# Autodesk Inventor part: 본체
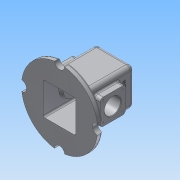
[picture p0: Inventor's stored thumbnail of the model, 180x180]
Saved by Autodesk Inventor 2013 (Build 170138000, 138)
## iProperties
Created: 2018-07
Part Number: 본체
Material: 알루미늄 6061
Document SubType Name: Modeling
Designer: Administrator
Density: 2.71 g/cm^3
Mass: 912.745 g
Surface Area: 1017.53 cm^2
Volume: 336.806 cm^3
Author: Administrator
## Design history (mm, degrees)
sketch "스케치1"
  geometry: L1 (-37, -37)-(37, -37); L2 (37, -37)-(37, 37); L3 (37, 37)-(-37, 37); L4 (-37, 37)-(-37, -37); L5 (-37, -37)-(37, 37); L6 (37, -37)-(-37, 37); 1 further point
  constraints: 12 end point, 2 midpoint, 2 parallel, 1 horizontal, 1 perpendicular
  dimensions: "d0" = 74 distance of L2.end L3.end; "d2" = 74 distance of L1.end L2.end
extrude "돌출1" new body sketch "스케치1" distance "d3" = 110; taper "d4" = 0 deg
feature "쉘1" dims "d5" = 5
sketch "스케치2"
  geometry: L1 (0, 0)-(74, 0) reference; L2 (12, 30)-(62, 30); L3 (62, 30)-(62, 80); L4 (62, 80)-(12, 80); L5 (12, 80)-(12, 30); L6 (12, 30)-(62, 80); L7 (62, 30)-(12, 80); 4 further points
  constraints: 12 end point, 4 midpoint, 2 parallel, 1 horizontal, 1 perpendicular, 1 vertical alignment
  dimensions: "d6" = 50 distance of L2.end L3.end; "d8" = 50 distance of L3.end L4.end; "d9" = 55 distance from line of L1 point (37, 55)
extrude "돌출2" join sketch "스케치2" distance "d10" = 13; taper "d11" = 0 deg
sketch "스케치3"
  geometry: L1 (0, 0)-(-64, 0) reference; C1 r 25 at (-32, 55); 2 further points
  constraints: 1 centre point, 1 midpoint, 1 vertical alignment
  dimensions: "d12" = 50 diameter of C1; "d13" = 55 distance from line of C1.centre L1
extrude "돌출3" join sketch "스케치3" distance "d14" = 7; taper "d15" = -20 deg
hole "구멍1" diameter "d18" = 32; stored, may be unused: countersink angle "d22" = 90 deg, drill point angle "d24" = 118 deg; dims "d16" = 10, "d17" = 10, "d19" = 6, "d20" = 4, "d21" = 2, "d23" = 8
sketch "스케치4"
  geometry: L1 (37, -37)-(-37, -37) reference; L2 (37, 37)-(37, -37) reference; L3 (-37, 37)-(37, 37) reference; L4 (-37, -37)-(-37, 37) reference; C1 r 75 at (0, 0); 1 further point
  constraints: 1 centre point, 1 coincident
  dimensions: "d25" = 150 diameter of C1
extrude "돌출4" join sketch "스케치4" distance "d26" = 10; taper "d27" = 0 deg
sketch "스케치5"
  geometry: L1 (-20, -20)-(20, -20); L2 (20, -20)-(20, 20); L3 (20, 20)-(-20, 20); L4 (-20, 20)-(-20, -20); L5 (-20, -20)-(20, 20); L6 (20, -20)-(-20, 20); 3 further points
  constraints: 12 end point, 3 midpoint, 2 parallel, 1 coincident, 1 horizontal, 1 perpendicular
  dimensions: "d28" = 40 distance of L1.end L2.end; "d30" = 40 distance of L2.end L3.end
extrude "돌출5" join sketch "스케치5" distance "d31" = 7; taper "d32" = 0 deg
sketch "스케치6"
  geometry: C1 r 17.5 at (0, 0); 1 further point
  constraints: 1 centre point, 1 coincident
  dimensions: "d33" = 35 diameter of C1
extrude "돌출6" join sketch "스케치6" distance "d34" = 3; taper "d35" = 0 deg
hole "구멍2" diameter "d38" = 21; stored, may be unused: countersink angle "d42" = 90 deg, drill point angle "d44" = 118 deg; dims "d36" = 10, "d37" = 10, "d39" = 6, "d40" = 28, "d41" = 4, "d43" = 8
sketch "스케치7"
  geometry: C1 r 10 at (-75, 0); C2 r 10 at (75, 0); C3 r 10 at (0, -75); C4 r 10 at (0, 75); A1 r 75 centre (0, 0) between (-75, 0) and (75, 0) reference
  constraints: 4 centre point, 4 point on circle, 2 horizontal alignment, 2 vertical alignment
  dimensions: "d46" = 20 diameter of C1; "d47" = 20 diameter of C2; "d48" = 20 diameter of C3; "d49" = 20 diameter of C4
extrude "돌출7" cut sketch "스케치7" stored distance "d50" = 3; taper "d51" = 0 deg
fillet "모깎기1" dims "d52" = 6
sketch "스케치8"
  geometry: A1 r 6 centre (56, 74) between (62, 74) and (56, 80) reference; A2 r 6 centre (18, 74) between (18, 80) and (12, 74) reference; A3 r 6 centre (18, 36) between (12, 36) and (18, 30) reference; A4 r 6 centre (56, 36) between (56, 30) and (62, 36) reference; 5 further points
  constraints: 4 coincident
hole "구멍3" sketch "스케치8" at (18, 74), (18, 36), (56, 36), (56, 74) diameter "d53" = 3.242; stored, may be unused: countersink angle "d57" = 82 deg, drill point angle "d59" = 118 deg; dims "d54" = 8, "d55" = 3.023, "d56" = 4, "d58" = 10
fillet "모깎기2" dims "d60" = 8
fillet "모깎기3" dims "d61" = 3
chamfer "모따기1" distance "d62" = 1; stored, may be unused: second distance "d63" = 2, angle "d64" = 45 deg
sketch "스케치9"
  geometry: L1 (46.5, 18)-(11.5, 18) reference; L2 (66, -89)-(66, 0) reference; 2 further points
  constraints: 1 other
  dimensions: "d65" = 30 distance from line of point (29, -12) L1; "d66" = 37 distance from line of L2 point (29, -12)
feature "엠보싱1" sketch "스케치9" dims "d0" = 74, "d2" = 74, "d67" = 0.5, "d68" = 0
node "솔리드1"
mirror "대칭1"
mirror "대칭2"
